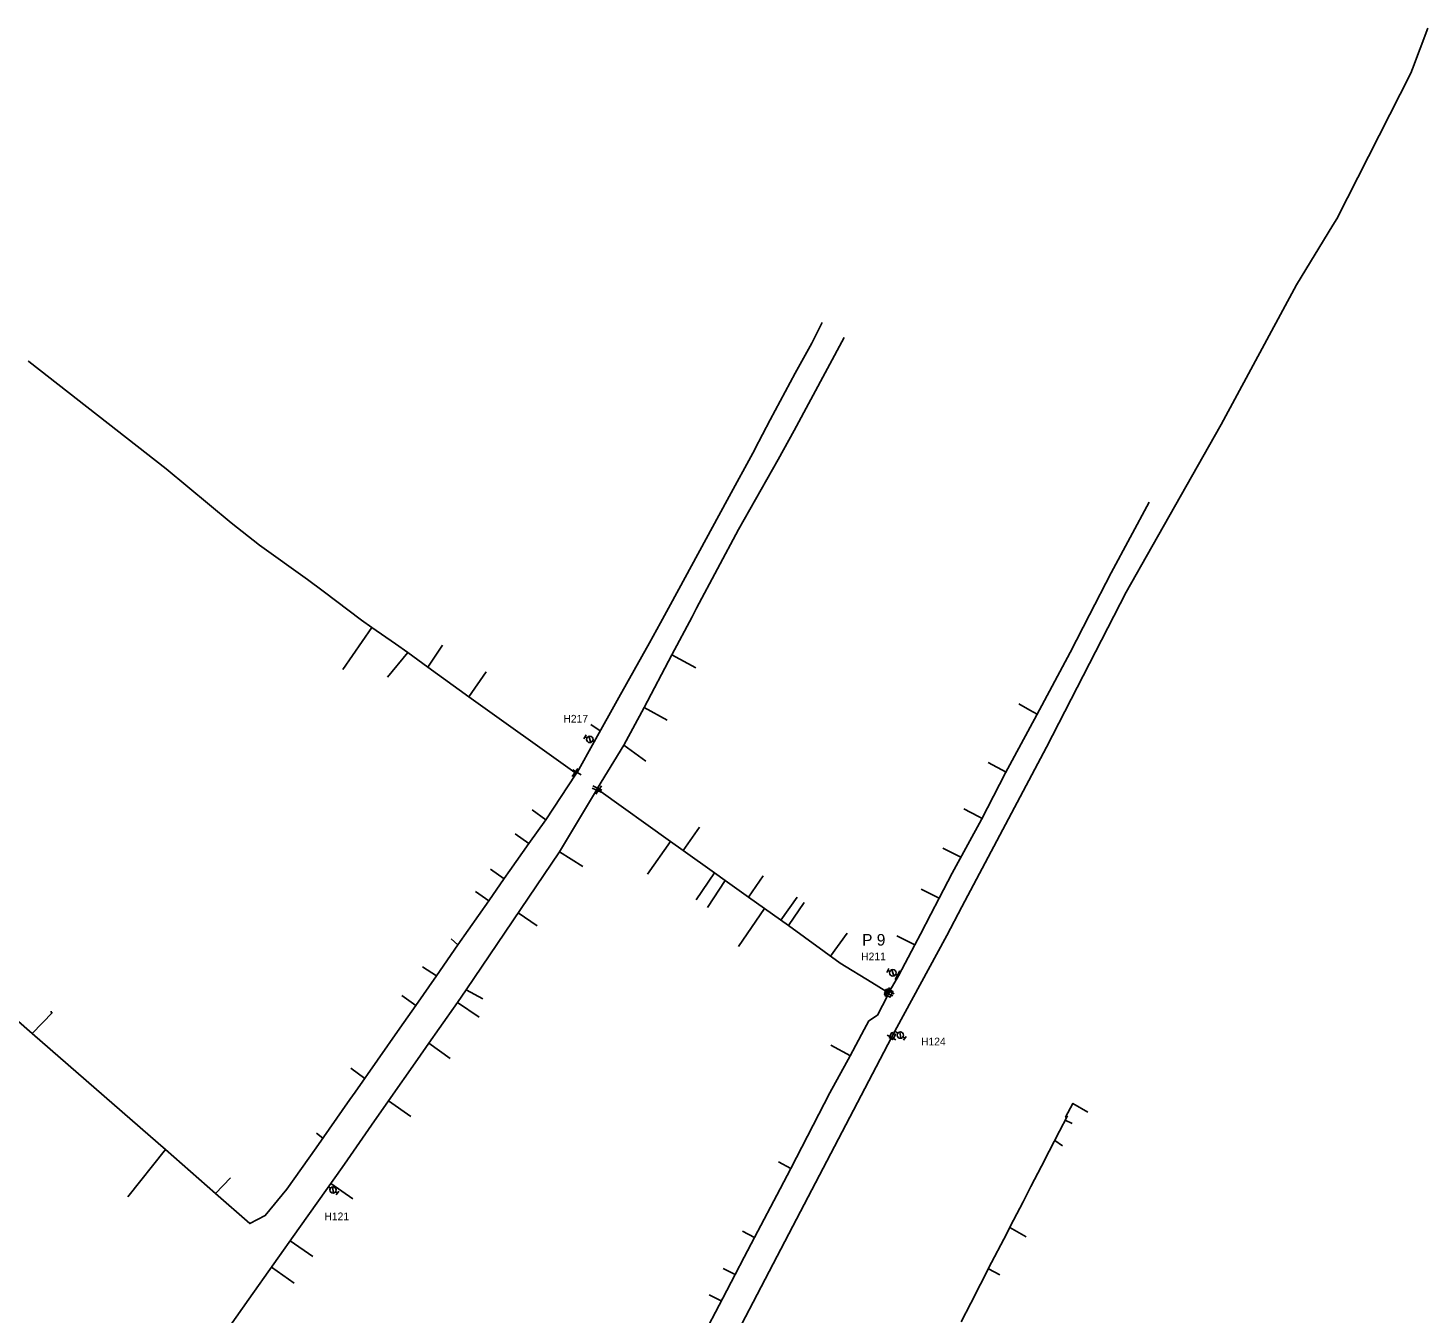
# Model space of a CAD drawing. Extents: x -548873 to -538270, y -1201997 to -1192514.
# Drawn here: x -544006.3 to -543643.1, y -1192847.4 to -1192513.9 of the extents above; entities that cross this region are included whole.
import ezdxf

# ---------------------------------------------------------------- set-up
doc = ezdxf.new("R2010")
doc.units = 0
for name, color, linetype in [('KN_HRAN_STÁTNÍ', 7, 'Continuous'), ('KN_PARC_Č', 7, 'Continuous'), ('KN_VKP_HRAN_SPORNÁ', 7, 'Continuous'), ('PK_PARC_Čv', 7, 'Continuous'), ('Vrstva 29', 7, 'Continuous')]:
    doc.layers.add(name, color=color, linetype=linetype)

# ---------------------------------------------------------------- blocks, each defined once
blk = doc.blocks.new('160')
at = {"layer": 'KN_HRAN_STÁTNÍ'}
blk.add_circle((0, 0), 0.0458, dxfattribs=at)
blk = doc.blocks.new('147')
at = {"layer": 'KN_HRAN_STÁTNÍ'}
blk.add_line((0, 1.27), (0, -1.27), dxfattribs=at)
blk = doc.blocks.new('133')
at = {"layer": 'KN_HRAN_STÁTNÍ'}
for p, q in [((0.28, 0), (0, 0)), ((0.54, 0.58), (1.7, -0.58)), ((1.94, 0), (2.52, 0)), ((2.52, 0.58), (2.52, -0.58))]:
    blk.add_line(p, q, dxfattribs=at)
blk.add_circle((1.11, 0), 0.825, dxfattribs=at)
blk = doc.blocks.new('150')
at = {"layer": 'KN_HRAN_STÁTNÍ'}
blk.add_line((0, 1.27), (0, -1.27), dxfattribs=at)

msp = doc.modelspace()

# ---------------------------------------------------------------- linework, layer by layer
at = {"layer": 'KN_PARC_Č'}
for points in [[(-543917.057, -1192669.34), (-543924.636, -1192680.232)], [(-543907.723, -1192675.829), (-543912.981, -1192682.202)], [(-543902.522, -1192679.614), (-543898.737, -1192673.941)], [(-543839.23, -1192676.435), (-543833.023, -1192679.814)], [(-543891.931, -1192687.321), (-543887.433, -1192680.819)], [(-543846.452, -1192690.096), (-543840.438, -1192693.388)], [(-543744.436, -1192691.852), (-543746.381, -1192690.749), (-543749.198, -1192689.153)], [(-543857.809, -1192696.165), (-543860.247, -1192694.536)], [(-543851.683, -1192699.877), (-543846.014, -1192703.983)], [(-543752.542, -1192706.858), (-543757.208, -1192704.39)], [(-543871.966, -1192719.212), (-543875.518, -1192716.633)], [(-543758.762, -1192718.894), (-543759.697, -1192718.398), (-543763.512, -1192716.374)], [(-543876.313, -1192725.386), (-543879.907, -1192722.88)], [(-543836.329, -1192727.168), (-543832.03, -1192721.112)], [(-543868.37, -1192727.543), (-543862.291, -1192731.329)], [(-543839.552, -1192724.876), (-543845.529, -1192733.29)], [(-543764.25, -1192728.92), (-543764.802, -1192728.644), (-543768.969, -1192726.555)], [(-543882.764, -1192734.549), (-543886.284, -1192732.064)], [(-543828.196, -1192732.949), (-543832.94, -1192739.97)], [(-543825.392, -1192734.942), (-543830.011, -1192741.942)], [(-543819.331, -1192739.251), (-543815.506, -1192733.783)], [(-543886.754, -1192740.216), (-543890.19, -1192737.817)], [(-543769.9, -1192739.587), (-543774.532, -1192737.168)], [(-543815.161, -1192742.215), (-543821.952, -1192752.069)], [(-543810.989, -1192745.231), (-543806.76, -1192739.296)], [(-543809.011, -1192746.662), (-543804.882, -1192740.635)], [(-543879.086, -1192743.354), (-543874.172, -1192746.684)], [(-543798.094, -1192754.555), (-543793.712, -1192748.616)], [(-543776.236, -1192751.679), (-543780.852, -1192749.269)], [(-543894.775, -1192751.608), (-543896.479, -1192750.119)], [(-543900.341, -1192759.675), (-543903.907, -1192757.325)], [(-543892.602, -1192763.296), (-543888.308, -1192765.646)], [(-543905.702, -1192767.362), (-543909.319, -1192764.786)], [(-543894.887, -1192766.568), (-543889.192, -1192770.424)], [(-544005.186, -1192774.648), (-543999.919, -1192769.167)], [(-544000.18, -1192769.438), (-544000.265, -1192768.868)], [(-543902.251, -1192777.112), (-543896.711, -1192781.087)], [(-543792.924, -1192780.409), (-543798.028, -1192777.7)], [(-543918.908, -1192786.3), (-543922.53, -1192783.602)], [(-543912.747, -1192792.142), (-543906.98, -1192796.191)], [(-543736.841, -1192796.473), (-543737.091, -1192796.311), (-543735.198, -1192792.78), (-543731.318, -1192795.083)], [(-543737.161, -1192797.092), (-543735.39, -1192798.01)], [(-543736.695, -1192796.191), (-543736.606, -1192796.012)], [(-543929.791, -1192801.785), (-543931.409, -1192800.493)], [(-543739.915, -1192802.421), (-543737.9, -1192803.75)], [(-543970.646, -1192804.727), (-543980.346, -1192816.992)], [(-543808.404, -1192809.611), (-543811.609, -1192807.957)], [(-543957.673, -1192816.118), (-543953.77, -1192812.05)], [(-543927.725, -1192813.521), (-543921.972, -1192817.555)], [(-543817.772, -1192827.521), (-543820.921, -1192825.88)], [(-543751.573, -1192824.974), (-543747.349, -1192827.332)], [(-543938.256, -1192828.4), (-543932.404, -1192832.493)], [(-543943.124, -1192835.278), (-543937.222, -1192839.392)], [(-543822.823, -1192837.155), (-543825.891, -1192835.554)], [(-543757.085, -1192835.638), (-543754.127, -1192837.236)], [(-543826.417, -1192844.007), (-543829.54, -1192842.374)]]:
    msp.add_lwpolyline(points, dxfattribs=at)
at = {"layer": 'KN_VKP_HRAN_SPORNÁ'}
for points in [[(-543782.269, -1192775.669), (-543781.412, -1192774.029), (-543767.889, -1192749.196), (-543763.985, -1192741.823), (-543742.038, -1192700.371), (-543721.407, -1192660.229), (-543714.693, -1192648.417), (-543696.684, -1192616.733), (-543677.181, -1192580.481), (-543667.754, -1192565.02), (-543666.725, -1192563.332), (-543647.544, -1192525.605), (-543647.096, -1192524.434), (-543643.06, -1192513.88)], [(-543800.24, -1192590.291), (-543802.933, -1192595.634), (-543807.254, -1192603.419), (-543813.745, -1192615.505), (-543817.678, -1192623.092), (-543817.708, -1192623.149), (-543824.866, -1192636.3), (-543839.584, -1192663.343), (-543842.196, -1192668.142), (-543845.066, -1192673.294), (-543853.006, -1192687.544), (-543859.389, -1192699), (-543863.816, -1192706.946)], [(-543794.558, -1192594.175), (-543807.476, -1192618.277), (-543811.683, -1192625.74), (-543821.939, -1192643.93), (-543832.806, -1192664.359), (-543833.989, -1192666.582), (-543839.23, -1192676.435), (-543846.452, -1192690.096), (-543851.683, -1192699.877), (-543858.567, -1192710.998)], [(-544006.208, -1192600.221), (-544006.109, -1192600.334), (-543970.473, -1192628.228), (-543953.567, -1192642.183), (-543946.198, -1192647.994), (-543933.76, -1192656.92), (-543929.719, -1192659.963), (-543919.732, -1192667.482), (-543917.057, -1192669.34), (-543910.976, -1192673.568), (-543907.723, -1192675.829), (-543902.522, -1192679.614), (-543891.931, -1192687.321), (-543864.37, -1192706.966)], [(-543715.43, -1192636.82), (-543725.28, -1192655.17), (-543730.84, -1192666.089), (-543735.93, -1192675.83), (-543744.52, -1192692.01), (-543752.64, -1192707.04), (-543758.9, -1192719.16), (-543766.52, -1192733.06), (-543769.9, -1192739.587), (-543772.04, -1192743.72), (-543774.76, -1192748.89), (-543776.236, -1192751.679), (-543780.46, -1192759.66), (-543782.564, -1192763.419), (-543782.752, -1192763.808)], [(-543948.707, -1192823.901), (-543957.673, -1192816.118), (-543970.646, -1192804.727), (-543972.53, -1192803.073), (-544005.186, -1192774.648), (-544017.286, -1192764.116), (-544018.343, -1192763.196), (-544018.547, -1192763.022), (-544026.658, -1192756.11), (-544034.41, -1192749.29), (-544035.465, -1192748.431), (-544041.089, -1192743.527), (-544049.48, -1192736.26), (-544084.409, -1192705.754), (-544092.765, -1192698.469)], [(-543864.003, -1192707.228), (-543864.134, -1192707.424), (-543871.966, -1192719.213), (-543876.313, -1192725.386), (-543881.256, -1192732.406), (-543882.71, -1192734.472), (-543886.754, -1192740.216), (-543894.775, -1192751.608), (-543900.341, -1192759.675), (-543905.702, -1192767.362), (-543909.785, -1192773.218), (-543921.401, -1192789.876), (-543922.756, -1192791.799), (-543931.535, -1192804.26), (-543939.114, -1192815.017), (-543944.75, -1192821.869), (-543948.707, -1192823.901)], [(-543864.37, -1192706.966), (-543864.003, -1192707.228)], [(-543863.816, -1192706.946), (-543864.003, -1192707.228)], [(-543988.04, -1192898.96), (-543979.677, -1192887.046), (-543969.055, -1192871.915), (-543964.242, -1192865.115), (-543948.948, -1192843.507), (-543936.009, -1192825.225), (-543926.274, -1192811.472), (-543924.182, -1192808.516), (-543917.149, -1192798.442), (-543912.747, -1192792.142), (-543905.218, -1192781.352), (-543902.251, -1192777.113), (-543899.603, -1192773.309), (-543894.887, -1192766.568), (-543892.602, -1192763.296), (-543868.371, -1192727.545), (-543858.752, -1192711.53)], [(-543858.752, -1192711.53), (-543858.647, -1192711.211)], [(-543858.567, -1192710.998), (-543858.647, -1192711.211)], [(-543858.647, -1192711.211), (-543858.213, -1192711.496)], [(-543858.213, -1192711.496), (-543839.552, -1192724.876), (-543836.329, -1192727.168), (-543828.196, -1192732.949), (-543825.392, -1192734.942), (-543819.331, -1192739.251), (-543815.161, -1192742.215), (-543809.009, -1192746.663), (-543795.562, -1192756.386), (-543787.368, -1192761.426), (-543783.69, -1192763.689), (-543783.329, -1192763.863)], [(-543783.015, -1192764.347), (-543783.274, -1192764.879), (-543785.89, -1192769.88), (-543788.15, -1192771.39), (-543789.32, -1192773.57), (-543792.94, -1192780.44), (-543798.219, -1192790.022), (-543808.404, -1192809.611), (-543811.18, -1192814.95), (-543817.772, -1192827.521), (-543820.44, -1192832.61), (-543822.823, -1192837.155), (-543826.03, -1192843.27), (-543831.64, -1192853.96), (-543838.077, -1192866.33), (-543841.373, -1192872.664), (-543841.74, -1192873.37), (-543849.469, -1192887.872), (-543851.19, -1192891.1), (-543851.239, -1192891.193), (-543858.64, -1192905.27), (-543861.61, -1192910.71), (-543866.65, -1192920.39)], [(-543783.329, -1192763.863), (-543782.884, -1192764.078)], [(-543782.884, -1192764.078), (-543783.015, -1192764.347)], [(-543782.752, -1192763.808), (-543782.884, -1192764.078)], [(-543978.302, -1193111.017), (-543977.92, -1193110.518), (-543974.99, -1193107.06), (-543958.629, -1193087.753), (-543946.124, -1193068.848), (-543922.134, -1193031.305), (-543916.932, -1193023.165), (-543901.182, -1192998.372), (-543892.761, -1192986.013), (-543892.217, -1192985.029), (-543888.198, -1192977.759), (-543878.838, -1192960.586), (-543859.8, -1192923.356), (-543852.208, -1192909.028), (-543844.617, -1192894.701), (-543830.409, -1192867.833), (-543807.844, -1192824.632), (-543782.269, -1192775.669)], [(-543764.185, -1192849.375), (-543761.683, -1192844.534), (-543759.137, -1192839.609), (-543756.272, -1192834.066), (-543753.107, -1192827.943), (-543750.579, -1192823.053), (-543748.128, -1192818.309), (-543746.063, -1192814.314), (-543743.347, -1192809.06), (-543741.316, -1192805.131), (-543738.659, -1192799.991), (-543736.695, -1192796.191)]]:
    msp.add_lwpolyline(points, dxfattribs=at)
at = {"layer": 'PK_PARC_Čv'}
for points in [[(-543859.389, -1192699), (-543859.543, -1192698.914)], [(-543780.46, -1192759.66), (-543780.69, -1192759.53), (-543780.9, -1192759.43)], [(-543783.37, -1192763.03), (-543781.88, -1192763.75), (-543782.59, -1192765.21), (-543784.08, -1192764.49), (-543783.37, -1192763.03)], [(-543782.834, -1192775.709), (-543781.907, -1192776.218), (-543781.229, -1192774.889), (-543782.155, -1192774.384), (-543782.834, -1192775.709)], [(-543781.412, -1192774.029), (-543780.86, -1192774.42)], [(-543928.329, -1192814.375), (-543928.046, -1192814.576)]]:
    msp.add_lwpolyline(points, dxfattribs=at)

# ---------------------------------------------------------------- block references
for name, p, xscale, yscale, rotation in [('133', (-543859.543, -1192698.914), 1.0037042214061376, 1.0037042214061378, 150.62079160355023), ('133', (-543780.9, -1192759.43), 1.0169562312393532, 1.016956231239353, 153.02398354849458), ('150', (-543780.69, -1192759.53), 1.0106518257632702, 1.0106518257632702, -28.16211573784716), ('133', (-543780.86, -1192774.42), 1.000000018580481, 1.000000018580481, -35.000000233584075), ('133', (-543928.046, -1192814.576), 1.000000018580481, 1.000000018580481, -35.000000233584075)]:
    msp.add_blockref(name, p, dxfattribs=dict(at, xscale=xscale, yscale=yscale, rotation=rotation))
at = {"layer": 'Vrstva 29'}
for name, p, xscale, yscale, rotation in [('147', (-543864.37, -1192706.966), 1.000000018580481, 1.000000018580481, -35.000000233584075), ('147', (-543863.816, -1192706.946), 1.0000000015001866, 1.0000000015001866, 59.00000017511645), ('160', (-543864.003, -1192707.228), 0.999999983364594, 0.9999999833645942, 101.0000002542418), ('147', (-543858.752, -1192711.53), 0.9999999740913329, 0.9999999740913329, -114.00000060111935), ('147', (-543858.567, -1192710.998), 1.0000000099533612, 1.0000000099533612, -116.000000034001), ('147', (-543858.213, -1192711.496), 0.9999999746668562, 0.999999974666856, 145.99999954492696), ('160', (-543858.647, -1192711.211), 0.999999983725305, 0.999999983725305, 109.00000122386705), ('147', (-543783.015, -1192764.347), 1.000000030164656, 1.000000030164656, -114.99999971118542), ('147', (-543783.329, -1192763.863), 1.0169562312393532, 1.016956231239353, 153.02398354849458), ('147', (-543782.752, -1192763.808), 1.000000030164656, 1.000000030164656, -114.99999971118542), ('160', (-543782.884, -1192764.078), 0.9999999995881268, 0.9999999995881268, -69.99999934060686), ('147', (-543782.269, -1192775.669), 0.9999999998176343, 0.9999999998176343, 63.00000066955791), ('160', (-543736.695, -1192796.191), 0.9999999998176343, 0.9999999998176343, -116.9999993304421), ('160', (-543948.707, -1192823.901), 1.0011217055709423, 1.0011217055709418, 173.41739016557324)]:
    msp.add_blockref(name, p, dxfattribs=dict(at, xscale=xscale, yscale=yscale, rotation=rotation))

# ---------------------------------------------------------------- texts
at = {"layer": 'PK_PARC_Čv'}
for s, height, p in [('H217', 2, (-543867.373, -1192694.014)), ('P 9', 3, (-543789.87, -1192751.84)), ('H211', 2, (-543790.12, -1192755.66)), ('H124', 2, (-543774.59, -1192777.72)), ('H121', 2, (-543929.376, -1192823.076))]:
    msp.add_text(s, height=height, dxfattribs=at).set_placement(p)

doc.saveas('drawing.dxf')
